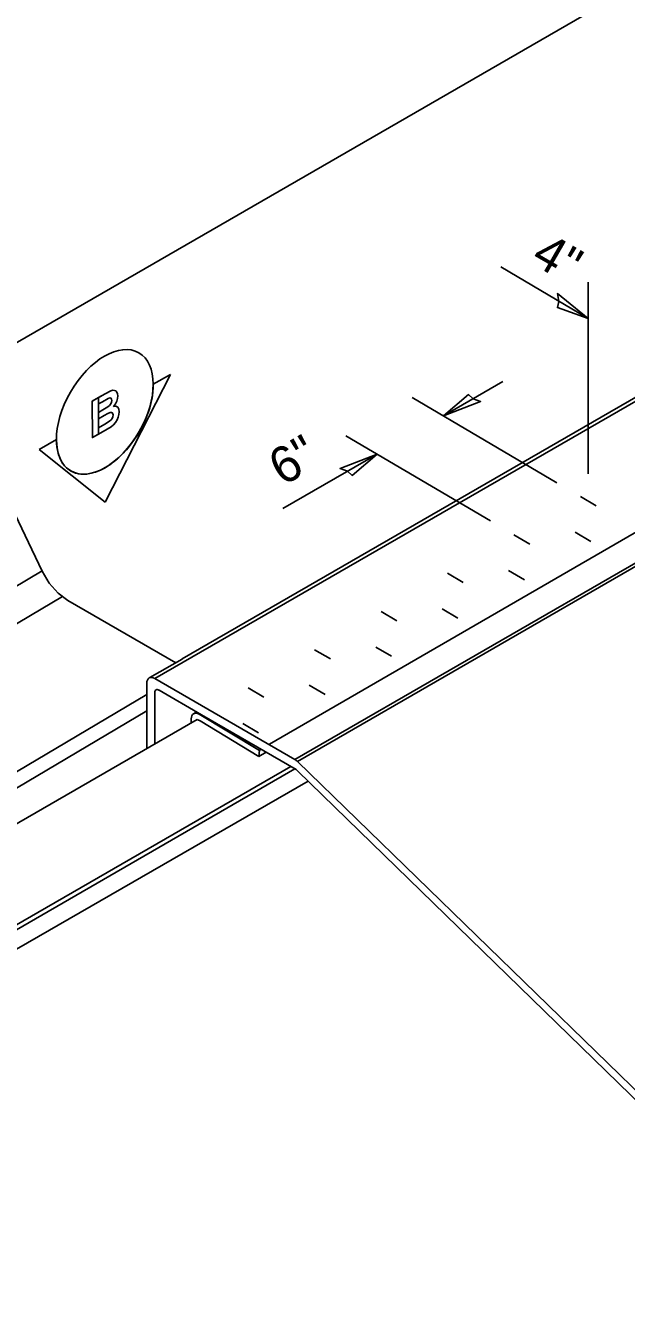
# Model space of a CAD drawing. Extents: x 99862 to 103151, y 100000 to 102076.
# Drawn here: x 100962 to 101226, y 101228 to 101791 of the extents above; entities that cross this region are included whole.
import ezdxf

# ---------------------------------------------------------------- set-up
doc = ezdxf.new("R2010")
doc.units = 0
for name, color, linetype in [('Level 1', 7, 'Continuous'), ('Level 15', 7, 'Continuous'), ('Level 2', 7, 'Continuous'), ('Level 20', 7, 'Continuous'), ('Level 3', 7, 'Continuous'), ('Level 36', 7, 'Continuous'), ('Level 7', 7, 'Continuous')]:
    doc.layers.add(name, color=color, linetype=linetype)

msp = doc.modelspace()

# ---------------------------------------------------------------- linework, layer by layer
at = {"layer": 'Level 1'}
msp.add_line((101086.21, 101458.4), (100787.82, 101286.48), dxfattribs=at)
msp.add_lwpolyline([(101602.37, 102023.9), (100916.96, 101628.18)], dxfattribs=at)
at = {"layer": 'Level 15'}
for p, q in [((101209.65, 101662.4), (101171.06, 101685.14)), ((101209.65, 101593.83), (101209.65, 101678.4)), ((101145.87, 101619.43), (101172.02, 101634.5)), ((101195.83, 101589.97), (101132.08, 101627.55)), ((101166.55, 101573.09), (101102.8, 101610.67)), ((101075, 101578.57), (101116.58, 101602.54))]:
    msp.add_line(p, q, dxfattribs=at)
for points in [[(101209.65, 101662.4), (101196.03, 101667.17), (101196.66, 101669.89), (101196.03, 101673.34)], [(101145.87, 101619.43), (101162.16, 101625.75), (101158.86, 101626.93), (101156.82, 101628.83)], [(101116.58, 101602.54), (101100.29, 101596.22), (101103.59, 101595.04), (101105.63, 101593.14)]]:
    msp.add_lwpolyline(points, close=True, dxfattribs=at)
at = {"layer": 'Level 2'}
for p, q in [((100714.94, 101400.61), (100968.94, 101551.1)), ((100724.03, 101389.35), (100977.95, 101539.79)), ((100779.31, 101356.9), (101015.11, 101496.6)), ((100782.17, 101351.32), (101015.11, 101489.37)), ((100825.65, 101318.87), (101078.53, 101464.87))]:
    msp.add_line(p, q, dxfattribs=at)
for points in [[(101027.83, 101510.58), (100980.24, 101538.06), (100975.99, 101541.27), (100972.13, 101545.69), (100969.02, 101550.92), (100944.88, 101601.17), (100938.15, 101612.69), (100929.46, 101621.95), (100920.03, 101627.69), (100911.16, 101629.1), (100904.08, 101625.99)], [(100794.82, 101337.71), (100794.82, 101343.79), (100795.08, 101345.17), (100795.81, 101346.05), (101037.34, 101485.5)], [(100824.51, 101315.92), (101080.26, 101463.87)]]:
    msp.add_lwpolyline(points, dxfattribs=at)
at = {"layer": 'Level 20'}
for p, q in [((101025.51, 101637.72), (100996.76, 101581.43)), ((100996.76, 101581.43), (101025.51, 101637.72)), ((101017.96, 101633.41), (101025.51, 101637.72)), ((101025.51, 101637.72), (101017.96, 101633.41)), ((100993.75, 101627.47), (100993.76, 101624.68)), ((100993.77, 101620.96), (100993.78, 101618.18)), ((100993.8, 101614.15), (100993.78, 101618.18)), ((100993.81, 101611.36), (100993.8, 101614.15)), ((100993.8, 101614.15), (100993.81, 101611.36)), ((100967.69, 101604.65), (100975.24, 101608.97)), ((100975.24, 101608.97), (100967.69, 101604.65)), ((100996.76, 101581.43), (100967.69, 101604.65)), ((100967.69, 101604.65), (100996.76, 101581.43))]:
    msp.add_line(p, q, dxfattribs=at)
for points in [[(101002.94, 101621.18), (101002.77, 101622.37), (101002.3, 101623.21), (101001.52, 101623.63), (101000.49, 101623.61), (101001.27, 101624.66), (101001.86, 101625.85), (101002.24, 101627.07), (101002.37, 101628.25), (101002.25, 101629.2), (101001.92, 101629.92), (101001.42, 101630.41), (101000.82, 101630.67), (101000.11, 101630.69), (100999.32, 101630.49), (100996.78, 101629.2), (100991.06, 101625.93), (100991.12, 101609.83), (100995.93, 101612.58), (100999.37, 101614.65), (101000.42, 101615.51), (101001.28, 101616.49), (101001.97, 101617.6), (101002.5, 101618.82), (101002.83, 101620.04), (101002.94, 101621.18)], [(100993.81, 101611.36), (100995.93, 101612.58), (100999.37, 101614.65), (101000.42, 101615.51), (101001.28, 101616.49), (101001.97, 101617.6), (101002.5, 101618.82), (101002.83, 101620.04), (101002.94, 101621.18), (101002.77, 101622.37), (101002.3, 101623.21), (101001.52, 101623.63), (101000.49, 101623.61), (101001.27, 101624.66), (101001.86, 101625.85), (101002.24, 101627.07), (101002.37, 101628.25), (101002.25, 101629.2), (101001.92, 101629.92), (101001.42, 101630.41), (101000.82, 101630.67), (101000.11, 101630.69), (100999.32, 101630.49), (100996.78, 101629.2), (100993.75, 101627.47)], [(100993.75, 101627.47), (100991.06, 101625.93), (100991.12, 101609.83), (100993.81, 101611.36)], [(100993.78, 101618.18), (100993.77, 101620.96), (100993.76, 101624.68), (100993.75, 101627.47)], [(100999.58, 101626.85), (100999.68, 101626.23), (100999.57, 101625.46), (100999.24, 101624.72), (100998.7, 101624.03), (100998, 101623.44), (100995.78, 101622.11), (100993.77, 101620.96), (100993.76, 101624.68), (100995.51, 101625.68), (100998.13, 101627.13), (100998.8, 101627.32), (100999.29, 101627.22), (100999.58, 101626.85)], [(100993.76, 101624.68), (100995.51, 101625.68), (100998.13, 101627.13), (100998.8, 101627.32), (100999.29, 101627.22), (100999.58, 101626.85), (100999.68, 101626.23), (100999.57, 101625.46), (100999.24, 101624.72), (100998.7, 101624.03), (100998, 101623.44), (100995.78, 101622.11), (100993.77, 101620.96)], [(101000.25, 101619.82), (101000.14, 101619.03), (100999.82, 101618.29), (100999.33, 101617.62), (100998.72, 101617.05), (100996.63, 101615.77), (100993.8, 101614.15), (100993.78, 101618.18), (100996.25, 101619.58), (100997.97, 101620.51), (100998.95, 101620.91), (100999.51, 101620.95), (100999.91, 101620.77), (101000.16, 101620.39), (101000.25, 101619.82)], [(100993.78, 101618.18), (100996.25, 101619.58), (100997.97, 101620.51), (100998.95, 101620.91), (100999.51, 101620.95), (100999.91, 101620.77), (101000.16, 101620.39), (101000.25, 101619.82), (101000.14, 101619.03), (100999.82, 101618.29), (100999.33, 101617.62), (100998.72, 101617.05), (100996.63, 101615.77), (100993.8, 101614.15)]]:
    msp.add_lwpolyline(points, dxfattribs=at)
msp.add_ellipse((100996.6, 101621.19), major_axis=(-15, -26.05), ratio=0.58137, dxfattribs=at)
msp.add_ellipse((100996.6, 101621.19), major_axis=(-15.04, -26.05), ratio=0.582661, start_param=5.497655, end_param=8.639269, dxfattribs=at)
msp.add_ellipse((100996.6, 101621.19), major_axis=(-15.04, -26.05), ratio=0.582661, start_param=5.497655, end_param=8.639269, dxfattribs=at)
at = {"layer": 'Level 3'}
for p, q in [((101273.2, 101650.61), (101018.64, 101503.64)), ((101030.62, 101512.24), (101270.7, 101650.85)), ((101334.93, 101614.92), (101080.37, 101467.95)), ((101336.08, 101614.04), (101081.52, 101467.07)), ((101016.5, 101504.04), (101030.65, 101512.2)), ((101030.65, 101512.2), (101030.62, 101512.24)), ((101015.11, 101472.66), (101015.11, 101501.68)), ((101039.21, 101491.72), (101018.62, 101503.6)), ((101018.64, 101474.7), (101018.64, 101497.51)), ((101020.41, 101498.53), (101020.5, 101498.48)), ((101020.49, 101498.44), (101039.17, 101487.66)), ((101037.05, 101488.88), (101035.74, 101488.09)), ((101064.78, 101471.95), (101038.16, 101487.89)), ((101039.17, 101487.66), (101080.98, 101463.46)), ((101039.21, 101491.72), (101080.37, 101467.95)), ((101034.71, 101485.8), (101034.71, 101483.98)), ((101064.46, 101469.27), (101038.56, 101484.94)), ((101064.46, 101469.27), (101064.79, 101472.02)), ((101064.46, 101469.27), (101067.69, 101471.14)), ((101064.79, 101472.02), (101065.49, 101472.42)), ((101348.28, 101207.36), (101081.52, 101467.07)), ((101081.55, 101462.94), (101347.07, 101204.22))]:
    msp.add_line(p, q, dxfattribs=at)
for centre, major_axis, start_param, end_param in [((101018.64, 101499.55), (2.5, -4.33), 2.356194, 3.949211), ((101020.41, 101496.49), (-1.25, 2.17), 5.497787, 6.283185), ((101020.41, 101496.49), (-1.25, 2.17), 0, 0.785398), ((101038.24, 101483.76), (2.5, -4.33), 3.141593, 3.926991), ((101038.24, 101483.76), (2.5, -4.33), 2.380579, 3.141593), ((101038.16, 101481.6), (-3.49, 3.58), 5.148721, 5.451711), ((101080.37, 101463.87), (2.5, -4.33), 2.025645, 2.356194), ((101080.34, 101459.81), (-2.5, 4.33), 5.148721, 5.317192)]:
    msp.add_ellipse(centre, major_axis=major_axis, ratio=0.57735, start_param=start_param, end_param=end_param, dxfattribs=at)
at = {"layer": 'Level 36'}
for p, q in [((101206.17, 101583.88), (101213.13, 101579.78)), ((101176.88, 101567), (101183.84, 101562.9)), ((101203.84, 101568.18), (101210.79, 101564.08)), ((101147.6, 101550.11), (101154.55, 101546.01)), ((101174.55, 101551.29), (101181.51, 101547.19)), ((101118.31, 101533.23), (101125.27, 101529.12)), ((101145.26, 101534.41), (101152.22, 101530.31)), ((101089.02, 101516.34), (101095.98, 101512.24)), ((101115.98, 101517.52), (101122.93, 101513.42)), ((101059.74, 101499.46), (101066.69, 101495.35)), ((101086.69, 101500.64), (101093.65, 101496.54)), ((101057.4, 101483.75), (101064.36, 101479.65))]:
    msp.add_line(p, q, dxfattribs=at)
at = {"layer": 'Level 7'}
msp.add_line((101069.2, 101474.71), (101323.52, 101621.91), dxfattribs=at)

# ---------------------------------------------------------------- texts
at = {"layer": 'Level 20'}
for s, rotation, p in [('4"', 330.0064, (101183.76, 101687.01)), ('6"', 29.9987, (101075.01, 101588.27))]:
    msp.add_text(s, height=16, rotation=rotation, dxfattribs=at).set_placement(p)

doc.saveas('drawing.dxf')
